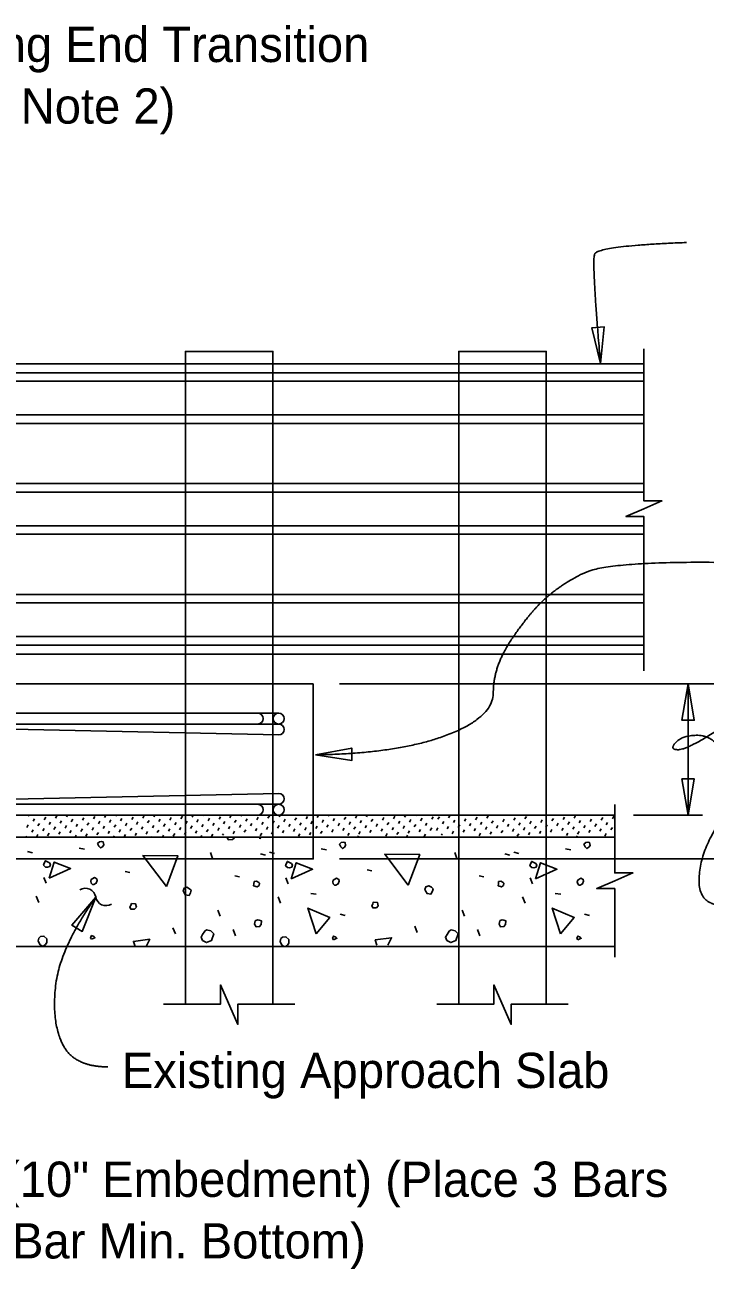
# Model space of a CAD drawing. Extents: x 1.5 to 68.7, y 0 to 31.
# Drawn here: x 32.97 to 36.86, y 9.34 to 16.45 of the extents above; entities that cross this region are included whole.
import ezdxf

# ---------------------------------------------------------------- set-up
doc = ezdxf.new("R2010")
doc.units = 0
for name, color, linetype in [('AdhocPoint_dp', 7, 'Continuous'), ('Border', 7, 'Continuous'), ('Patterning', 7, 'Continuous'), ('PlotBorder_dp', 7, 'Continuous'), ('TextMisc', 7, 'Continuous')]:
    doc.layers.add(name, color=color, linetype=linetype)

# ---------------------------------------------------------------- blocks, each defined once
blk = doc.blocks.new('Terminator-Arrow')
at = {"layer": 'AdhocPoint_dp'}
blk.add_lwpolyline([(0, 0), (-0.00041, 0.000069), (-0.00041, -0.000069)], close=True, dxfattribs=at)

msp = doc.modelspace()

# ---------------------------------------------------------------- linework, layer by layer
at = {"layer": 'AdhocPoint_dp'}
for p, q in [((34.7705, 12.682), (37.7448, 12.682)), ((36.763, 12.682), (36.763, 11.932)), ((36.4509, 11.932), (36.8456, 11.932)), ((34.7705, 11.682), (37.7448, 11.682))]:
    msp.add_line(p, q, dxfattribs=at)
for points in [[(36.2627, 14.5121), (36.2835, 14.7223), (36.2131, 14.7174)], [(34.6328, 12.277), (34.8416, 12.2452), (34.8404, 12.3157)], [(33.3771, 11.4646), (33.2393, 11.3045), (33.2997, 11.268)]]:
    msp.add_lwpolyline(points, close=True, dxfattribs=at)
for points in [[(36.5106, 12.7576), (36.5106, 13.6381), (36.4073, 13.6381), (36.5106, 13.6831), (36.6139, 13.7281), (36.5106, 13.7281), (36.5106, 14.5965)], [(36.3442, 11.1206), (36.3442, 11.5124), (36.2408, 11.5124), (36.3442, 11.5574), (36.4475, 11.6024), (36.3442, 11.6024), (36.3442, 11.9928)], [(34.5149, 10.8531), (34.1896, 10.8531), (34.1896, 10.7369), (34.0902, 10.9619), (34.0902, 10.8531), (33.7649, 10.8531)], [(36.0774, 10.8531), (35.7521, 10.8531), (35.7521, 10.7369), (35.6527, 10.9619), (35.6527, 10.8531), (35.3274, 10.8531)]]:
    msp.add_lwpolyline(points, dxfattribs=at)
for centre, start, end in [((33.3177, 11.455), 9.45289, 121.18011), ((33.4353, 11.4746), 189.45289, 301.18011)]:
    msp.add_arc(centre, 0.0596, start, end, dxfattribs=at)
for points in [[(36.7547, 15.2044), (36.2452, 15.1849), (36.212, 15.0904), (36.2626, 14.512)], [(36.9638, 13.3766), (36.3023, 13.3835), (36.0282, 13.2463), (35.8452, 13.0751), (35.6496, 12.7777), (35.6496, 12.4881), (35.1021, 12.2847), (34.6328, 12.2768)], [(36.9767, 11.4144), (36.8259, 11.4144), (36.8259, 11.6957), (37.0041, 11.9975), (37.0041, 12.217), (36.9013, 12.3885), (36.7299, 12.3885), (36.6545, 12.3062), (36.7573, 12.3062), (36.9287, 12.416)], [(33.4454, 10.4942), (33.2528, 10.4942), (33.1238, 10.7493), (33.172, 11.1721), (33.3771, 11.4644)]]:
    msp.add_open_spline(points, degree=2, dxfattribs=at)
at = {"layer": 'Border'}
for p, q in [((30.7872, 12.5153), (34.4226, 12.5153)), ((30.7872, 12.4528), (34.4226, 12.4528)), ((34.4226, 12.3904), (31.6205, 12.4528)), ((34.4226, 12.0569), (31.6205, 11.9945)), ((30.7872, 11.9945), (34.4226, 11.9945)), ((30.7872, 11.932), (34.4226, 11.932))]:
    msp.add_line(p, q, dxfattribs=at)
for centre in [(34.4226, 12.484), (34.4226, 11.9632)]:
    msp.add_circle(centre, 0.0312, dxfattribs=at)
for centre in [(34.3024, 12.4841), (34.4226, 12.4216), (34.4226, 12.4216), (34.4226, 12.0257), (34.3024, 11.9633)]:
    msp.add_arc(centre, 0.0312, 270, 90, dxfattribs=at)
at = {"layer": 'Patterning'}
for p, q in [((29.5056, 14.512), (36.5106, 14.512)), ((30.1632, 14.4598), (36.5106, 14.4598)), ((30.1645, 14.4116), (36.5106, 14.4116)), ((30.1692, 14.2188), (36.5106, 14.2188)), ((30.1703, 14.1705), (36.5106, 14.1705)), ((30.1669, 13.8266), (36.5106, 13.8266)), ((30.1656, 13.7783), (36.5106, 13.7783)), ((30.1604, 13.5855), (36.5106, 13.5855)), ((30.1563, 13.5374), (36.5106, 13.5374)), ((30.1703, 13.1934), (36.5106, 13.1934)), ((30.1692, 13.1452), (36.5106, 13.1452)), ((30.1629, 12.9524), (36.5106, 12.9524)), ((30.164, 12.9042), (36.5106, 12.9042)), ((29.5056, 12.8519), (36.5106, 12.8519)), ((32.9832, 11.8622), (32.9913, 11.8762)), ((32.9913, 11.9257), (32.9949, 11.932)), ((33.019, 11.898), (33.0271, 11.912)), ((33.0467, 11.8703), (33.0548, 11.8843)), ((33.0825, 11.9061), (33.0906, 11.9201)), ((33.1101, 11.8784), (33.1182, 11.8924)), ((33.1459, 11.9142), (33.154, 11.9282)), ((33.1736, 11.8865), (33.1817, 11.9005)), ((33.2013, 11.8588), (33.2094, 11.8728)), ((33.2094, 11.9223), (33.215, 11.932)), ((33.2371, 11.8946), (33.2452, 11.9086)), ((33.2648, 11.8669), (33.2729, 11.8809)), ((33.2729, 11.9304), (33.2738, 11.932)), ((33.3006, 11.9027), (33.3087, 11.9167)), ((33.3283, 11.875), (33.3364, 11.889)), ((33.3641, 11.9108), (33.3722, 11.9248)), ((33.3918, 11.8831), (33.3999, 11.8971)), ((33.4276, 11.9189), (33.4352, 11.932)), ((33.4553, 11.8912), (33.4634, 11.9052)), ((33.483, 11.8635), (33.4911, 11.8775)), ((33.4911, 11.927), (33.494, 11.932)), ((33.5188, 11.8993), (33.5269, 11.9133)), ((33.5465, 11.8716), (33.5546, 11.8856)), ((33.5823, 11.9074), (33.5904, 11.9214)), ((33.61, 11.8797), (33.6181, 11.8937)), ((33.6458, 11.9155), (33.6539, 11.9295)), ((33.6735, 11.8878), (33.6816, 11.9018)), ((33.7012, 11.8601), (33.7093, 11.8741)), ((33.7093, 11.9236), (33.7141, 11.932)), ((33.737, 11.8959), (33.7451, 11.9099)), ((33.7647, 11.8682), (33.7728, 11.8822)), ((33.7728, 11.9317), (33.7729, 11.932)), ((33.8005, 11.904), (33.8086, 11.918)), ((33.8282, 11.8763), (33.8363, 11.8903)), ((33.864, 11.9121), (33.8721, 11.9261)), ((33.8916, 11.8844), (33.8997, 11.8984)), ((33.9274, 11.9202), (33.9342, 11.932)), ((33.9551, 11.8925), (33.9632, 11.9065)), ((33.9828, 11.8648), (33.9909, 11.8788)), ((33.9909, 11.9283), (33.993, 11.932)), ((34.0186, 11.9006), (34.0267, 11.9146)), ((34.0463, 11.873), (34.0544, 11.8869)), ((34.0821, 11.9087), (34.0902, 11.9227)), ((34.1072, 11.8818), (34.1153, 11.8958)), ((34.143, 11.9176), (34.1511, 11.9316)), ((34.1707, 11.8899), (34.1788, 11.9039)), ((34.1984, 11.8622), (34.2065, 11.8762)), ((34.2065, 11.9257), (34.2102, 11.932)), ((34.2342, 11.898), (34.2423, 11.912)), ((34.2619, 11.8703), (34.27, 11.8843)), ((34.2977, 11.9061), (34.3058, 11.9201)), ((34.3254, 11.8784), (34.3335, 11.8924)), ((34.3612, 11.9142), (34.3693, 11.9282)), ((34.3889, 11.8865), (34.397, 11.9005)), ((34.4166, 11.8588), (34.4247, 11.8728)), ((34.4247, 11.9223), (34.4303, 11.932)), ((34.4524, 11.8946), (34.4605, 11.9086)), ((34.4801, 11.8669), (34.4882, 11.8809)), ((34.4882, 11.9304), (34.4891, 11.932)), ((34.5159, 11.9027), (34.524, 11.9167)), ((34.5436, 11.875), (34.5517, 11.889)), ((34.5794, 11.9108), (34.5875, 11.9248)), ((34.6071, 11.8831), (34.6152, 11.8971)), ((34.6429, 11.9189), (34.6504, 11.932)), ((34.6706, 11.8912), (34.6787, 11.9052)), ((34.6983, 11.8635), (34.7064, 11.8775)), ((34.7064, 11.927), (34.7092, 11.932)), ((34.7341, 11.8993), (34.7422, 11.9133)), ((34.7618, 11.8716), (34.7699, 11.8856)), ((34.7975, 11.9074), (34.8057, 11.9214)), ((34.8252, 11.8797), (34.8333, 11.8937)), ((34.861, 11.9155), (34.8691, 11.9295)), ((34.8887, 11.8878), (34.8968, 11.9018)), ((34.9164, 11.8601), (34.9245, 11.8741)), ((34.9245, 11.9236), (34.9294, 11.932)), ((34.9522, 11.8959), (34.9603, 11.9099)), ((34.9799, 11.8682), (34.988, 11.8822)), ((34.988, 11.9317), (34.9882, 11.932)), ((35.0157, 11.904), (35.0238, 11.918)), ((35.0434, 11.8763), (35.0515, 11.8903)), ((35.0792, 11.9121), (35.0873, 11.9261)), ((35.1069, 11.8844), (35.115, 11.8984)), ((35.1427, 11.9202), (35.1495, 11.932)), ((35.1704, 11.8925), (35.1785, 11.9065)), ((35.1981, 11.8648), (35.2062, 11.8788)), ((35.2062, 11.9283), (35.2083, 11.932)), ((35.2339, 11.9006), (35.242, 11.9146)), ((35.2616, 11.873), (35.2697, 11.8869)), ((35.2974, 11.9087), (35.3055, 11.9227)), ((35.3331, 11.9087), (35.3412, 11.9227)), ((35.3583, 11.8818), (35.3664, 11.8958)), ((35.3941, 11.9176), (35.4022, 11.9316)), ((35.4217, 11.8899), (35.4298, 11.9039)), ((35.4494, 11.8622), (35.4575, 11.8762)), ((35.4852, 11.898), (35.4933, 11.912)), ((35.5129, 11.8703), (35.521, 11.8843)), ((35.5487, 11.9061), (35.5568, 11.9201)), ((35.5764, 11.8784), (35.5845, 11.8924)), ((35.6122, 11.9142), (35.6203, 11.9282)), ((35.6399, 11.8865), (35.648, 11.9005)), ((35.6676, 11.8588), (35.6757, 11.8728)), ((35.7034, 11.8946), (35.7115, 11.9086)), ((35.7311, 11.8669), (35.7392, 11.8809)), ((35.7669, 11.9027), (35.775, 11.9167)), ((35.7946, 11.875), (35.8027, 11.889)), ((35.8304, 11.9108), (35.8385, 11.9248)), ((35.8581, 11.8831), (35.8662, 11.8971)), ((35.9216, 11.8912), (35.9297, 11.9052)), ((35.9493, 11.8635), (35.9574, 11.8775)), ((35.9851, 11.8993), (35.9932, 11.9133)), ((36.0128, 11.8716), (36.0209, 11.8856)), ((36.0486, 11.9074), (36.0567, 11.9214)), ((36.0763, 11.8797), (36.0844, 11.8937)), ((36.1121, 11.9155), (36.1202, 11.9295)), ((36.1398, 11.8878), (36.1479, 11.9018)), ((36.1675, 11.8601), (36.1756, 11.8741)), ((36.2032, 11.8959), (36.2113, 11.9099)), ((36.2309, 11.8682), (36.239, 11.8822)), ((36.2667, 11.904), (36.2748, 11.918)), ((36.2944, 11.8763), (36.3025, 11.8903)), ((36.3302, 11.9121), (36.3383, 11.9261)), ((32.9798, 11.807), (32.9832, 11.8127)), ((33.0109, 11.8345), (33.019, 11.8485)), ((33.0386, 11.807), (33.0467, 11.8208)), ((33.0743, 11.8426), (33.0825, 11.8566)), ((33.102, 11.8149), (33.1101, 11.8289)), ((33.1378, 11.8507), (33.1459, 11.8647)), ((33.1655, 11.823), (33.1736, 11.837)), ((33.2, 11.807), (33.2013, 11.8093)), ((33.229, 11.8311), (33.2371, 11.8451)), ((33.2588, 11.807), (33.2648, 11.8174)), ((33.2925, 11.8392), (33.3006, 11.8532)), ((33.3202, 11.8115), (33.3283, 11.8255)), ((33.356, 11.8473), (33.3641, 11.8613)), ((33.3837, 11.8196), (33.3918, 11.8336)), ((33.4195, 11.8554), (33.4276, 11.8694)), ((33.4472, 11.8277), (33.4553, 11.8417)), ((33.4789, 11.807), (33.483, 11.814)), ((33.5107, 11.8358), (33.5188, 11.8498)), ((33.5384, 11.8081), (33.5465, 11.8221)), ((33.5742, 11.8439), (33.5823, 11.8579)), ((33.6019, 11.8162), (33.61, 11.8302)), ((33.6377, 11.852), (33.6458, 11.866)), ((33.6654, 11.8243), (33.6735, 11.8383)), ((33.6991, 11.807), (33.7012, 11.8106)), ((33.7289, 11.8324), (33.737, 11.8464)), ((33.7579, 11.807), (33.7647, 11.8187)), ((33.7924, 11.8405), (33.8005, 11.8545)), ((33.8201, 11.8128), (33.8282, 11.8268)), ((33.8558, 11.8486), (33.864, 11.8626)), ((33.8835, 11.8209), (33.8916, 11.8349)), ((33.9192, 11.807), (33.9193, 11.8072)), ((33.9193, 11.8567), (33.9274, 11.8707)), ((33.947, 11.8291), (33.9551, 11.843)), ((33.978, 11.807), (33.9828, 11.8154)), ((34.0105, 11.8372), (34.0186, 11.8511)), ((34.0382, 11.8095), (34.0463, 11.8235)), ((34.074, 11.8453), (34.0821, 11.8593)), ((34.1017, 11.8176), (34.1067, 11.8263)), ((34.1349, 11.8541), (34.143, 11.8681)), ((34.1626, 11.8264), (34.1707, 11.8404)), ((34.2261, 11.8345), (34.2342, 11.8485)), ((34.2896, 11.8426), (34.2977, 11.8566)), ((34.3173, 11.8149), (34.3254, 11.8289)), ((34.3531, 11.8507), (34.3612, 11.8647)), ((34.3808, 11.823), (34.3889, 11.837)), ((34.4443, 11.8311), (34.4524, 11.8451)), ((34.5078, 11.8392), (34.5159, 11.8532)), ((34.5355, 11.8115), (34.5436, 11.8255)), ((34.5713, 11.8473), (34.5794, 11.8613)), ((34.595, 11.807), (34.5964, 11.8093)), ((34.599, 11.8196), (34.6071, 11.8336)), ((34.6348, 11.8554), (34.6429, 11.8694)), ((34.6625, 11.8277), (34.6706, 11.8417)), ((34.726, 11.8358), (34.7341, 11.8498)), ((34.7894, 11.8439), (34.7975, 11.8579)), ((34.8171, 11.8162), (34.8252, 11.8302)), ((34.8529, 11.852), (34.861, 11.866)), ((34.874, 11.807), (34.8781, 11.814)), ((34.8806, 11.8243), (34.8887, 11.8383)), ((34.9441, 11.8324), (34.9522, 11.8464)), ((35.0076, 11.8405), (35.0157, 11.8545)), ((35.0353, 11.8128), (35.0434, 11.8268)), ((35.0711, 11.8486), (35.0792, 11.8626)), ((35.0941, 11.807), (35.0962, 11.8106)), ((35.0988, 11.8209), (35.1069, 11.8349)), ((35.1346, 11.8567), (35.1427, 11.8707)), ((35.1529, 11.807), (35.1597, 11.8187)), ((35.1623, 11.8291), (35.1704, 11.843)), ((35.2258, 11.8372), (35.2339, 11.8511)), ((35.2535, 11.8095), (35.2616, 11.8235)), ((35.2893, 11.8453), (35.2974, 11.8593)), ((35.325, 11.8453), (35.3331, 11.8593)), ((35.3527, 11.8176), (35.3578, 11.8263)), ((35.3859, 11.8541), (35.3941, 11.8681)), ((35.4136, 11.8264), (35.4217, 11.8404)), ((35.4771, 11.8345), (35.4852, 11.8485)), ((35.5406, 11.8426), (35.5487, 11.8566)), ((35.5683, 11.8149), (35.5764, 11.8289)), ((35.6041, 11.8507), (35.6122, 11.8647)), ((35.6318, 11.823), (35.6399, 11.837)), ((35.6953, 11.8311), (35.7034, 11.8451)), ((35.7588, 11.8392), (35.7669, 11.8532)), ((35.7865, 11.8115), (35.7946, 11.8255)), ((35.8223, 11.8473), (35.8304, 11.8613)), ((35.8461, 11.807), (35.8474, 11.8093)), ((35.85, 11.8196), (35.8581, 11.8336)), ((35.8858, 11.8554), (35.8939, 11.8694)), ((35.9135, 11.8277), (35.9216, 11.8417)), ((35.977, 11.8358), (35.9851, 11.8498)), ((36.0405, 11.8439), (36.0486, 11.8579)), ((36.0682, 11.8162), (36.0763, 11.8302)), ((36.104, 11.852), (36.1121, 11.866)), ((36.125, 11.807), (36.1291, 11.814)), ((36.1317, 11.8243), (36.1398, 11.8383)), ((36.1951, 11.8324), (36.2032, 11.8464)), ((36.2586, 11.8405), (36.2667, 11.8545)), ((36.2863, 11.8128), (36.2944, 11.8268)), ((36.3221, 11.8486), (36.3302, 11.8626)), ((33.2826, 11.7433), (33.3126, 11.738)), ((34.6659, 11.7398), (34.6959, 11.7345)), ((36.0629, 11.7398), (36.093, 11.7345)), ((32.9869, 11.7243), (33.0152, 11.7173)), ((34.0445, 11.685), (34.0321, 11.7186)), ((34.3185, 11.7115), (34.3468, 11.7045)), ((34.3702, 11.7208), (34.3985, 11.7137)), ((35.4416, 11.685), (35.4292, 11.7186)), ((35.7156, 11.7115), (35.7439, 11.7045)), ((35.7673, 11.7208), (35.7956, 11.7137)), ((33.546, 11.6108), (33.5725, 11.6055)), ((34.9283, 11.619), (34.9549, 11.6137)), ((33.093, 11.5431), (33.0806, 11.5767)), ((34.1718, 11.586), (34.1983, 11.5807)), ((34.4763, 11.5396), (34.4639, 11.5732)), ((35.5689, 11.586), (35.5954, 11.5807)), ((35.8734, 11.5396), (35.861, 11.5732)), ((33.0506, 11.4335), (33.0364, 11.4689)), ((34.4338, 11.43), (34.4197, 11.4654)), ((34.6058, 11.4852), (34.6376, 11.4817)), ((35.8309, 11.43), (35.8168, 11.4654)), ((36.0028, 11.4852), (36.0347, 11.4817)), ((34.0887, 11.3544), (34.0745, 11.3898)), ((35.4858, 11.3544), (35.4716, 11.3898)), ((34.7737, 11.3668), (34.802, 11.3597)), ((36.1708, 11.3668), (36.1991, 11.3597)), ((33.8324, 11.2537), (33.8182, 11.289)), ((34.1757, 11.2426), (34.1616, 11.278)), ((35.2147, 11.2619), (35.2006, 11.2972)), ((35.5728, 11.2426), (35.5587, 11.278))]:
    msp.add_line(p, q, dxfattribs=at)
for points in [[(34.3899, 10.853), (34.3899, 14.5819), (33.8899, 14.5819), (33.8899, 10.853)], [(35.9524, 10.853), (35.9524, 14.5819), (35.4524, 14.5819), (35.4524, 10.853)], [(34.1266, 11.8069), (34.1364, 11.7911), (34.1594, 11.7928), (34.1682, 11.8017), (34.1735, 11.8069)], [(34.3154, 11.7968), (34.3121, 11.8069)], [(34.3206, 11.8069), (34.3154, 11.7968)], [(33.3939, 11.7557), (33.4046, 11.7451), (33.4152, 11.7522), (33.4222, 11.7628), (33.4187, 11.7805), (33.4099, 11.7822), (33.3975, 11.7805), (33.3869, 11.7699), (33.3939, 11.7557)], [(34.7772, 11.7522), (34.7878, 11.7416), (34.7984, 11.7486), (34.8055, 11.7593), (34.802, 11.7769), (34.7931, 11.7787), (34.7808, 11.7769), (34.7702, 11.7663), (34.7772, 11.7522)], [(36.1743, 11.7522), (36.1849, 11.7416), (36.1955, 11.7486), (36.2026, 11.7593), (36.1991, 11.7769), (36.1902, 11.7787), (36.1778, 11.7769), (36.1672, 11.7663), (36.1743, 11.7522)], [(33.0895, 11.636), (33.1018, 11.6342), (33.1142, 11.6395), (33.1177, 11.6501), (33.1124, 11.6589), (33.1018, 11.666), (33.0895, 11.6713), (33.0824, 11.6572), (33.0788, 11.6466), (33.0895, 11.636)], [(33.1111, 11.5719), (33.1394, 11.6638), (33.2331, 11.6267), (33.1111, 11.5719)], [(33.7811, 11.5241), (33.6467, 11.7009), (33.8465, 11.6991), (33.7811, 11.5241)], [(34.4727, 11.6324), (34.4851, 11.6306), (34.4975, 11.636), (34.501, 11.6466), (34.4957, 11.6554), (34.4851, 11.6625), (34.4727, 11.6678), (34.4657, 11.6536), (34.4621, 11.643), (34.4727, 11.6324)], [(34.4944, 11.5683), (34.5227, 11.6603), (34.6164, 11.6231), (34.4944, 11.5683)], [(35.1634, 11.5323), (35.0291, 11.7091), (35.2289, 11.7074), (35.1634, 11.5323)], [(35.8698, 11.6324), (35.8822, 11.6306), (35.8946, 11.636), (35.8981, 11.6466), (35.8928, 11.6554), (35.8822, 11.6625), (35.8698, 11.6678), (35.8627, 11.6536), (35.8592, 11.643), (35.8698, 11.6324)], [(35.8915, 11.5683), (35.9198, 11.6603), (36.0134, 11.6231), (35.8915, 11.5683)], [(33.3586, 11.5365), (33.3657, 11.5365), (33.3798, 11.5436), (33.3851, 11.5595), (33.3833, 11.5683), (33.3692, 11.5754), (33.3515, 11.5648), (33.348, 11.5542), (33.3515, 11.5436), (33.3586, 11.5365)], [(33.8801, 11.4923), (33.8889, 11.4764), (33.9101, 11.4729), (33.919, 11.4888), (33.9225, 11.5029), (33.9137, 11.5118), (33.8978, 11.5206), (33.8819, 11.5153), (33.8765, 11.4994), (33.8801, 11.4923)], [(34.2796, 11.5277), (34.299, 11.5224), (34.3114, 11.5312), (34.3132, 11.5436), (34.3097, 11.5471), (34.2955, 11.5542), (34.2831, 11.5524), (34.2814, 11.54), (34.2796, 11.5277)], [(34.7419, 11.533), (34.7489, 11.533), (34.7631, 11.54), (34.7684, 11.556), (34.7666, 11.5648), (34.7525, 11.5719), (34.7348, 11.5613), (34.7313, 11.5507), (34.7348, 11.54), (34.7419, 11.533)], [(35.2624, 11.5005), (35.2713, 11.4846), (35.2925, 11.4811), (35.3013, 11.497), (35.3049, 11.5111), (35.296, 11.52), (35.2801, 11.5288), (35.2642, 11.5235), (35.2589, 11.5076), (35.2624, 11.5005)], [(35.6767, 11.5277), (35.6961, 11.5224), (35.7085, 11.5312), (35.7103, 11.5436), (35.7067, 11.5471), (35.6926, 11.5542), (35.6802, 11.5524), (35.6785, 11.54), (35.6767, 11.5277)], [(36.139, 11.533), (36.146, 11.533), (36.1602, 11.54), (36.1655, 11.556), (36.1637, 11.5648), (36.1496, 11.5719), (36.1319, 11.5613), (36.1284, 11.5507), (36.1319, 11.54), (36.139, 11.533)], [(33.5778, 11.3951), (33.599, 11.3951), (33.6096, 11.4057), (33.6043, 11.4251), (33.5813, 11.4269), (33.5778, 11.4163), (33.5725, 11.4075), (33.5778, 11.3951), (33.5743, 11.3986)], [(34.6371, 11.255), (34.5894, 11.4017), (34.7149, 11.3469), (34.6371, 11.255)], [(34.9602, 11.4033), (34.9814, 11.4033), (34.992, 11.4139), (34.9867, 11.4334), (34.9637, 11.4351), (34.9602, 11.4245), (34.9549, 11.4157), (34.9602, 11.4033), (34.9566, 11.4068)], [(36.0342, 11.255), (35.9865, 11.4017), (36.112, 11.3469), (36.0342, 11.255)], [(34.2853, 11.3098), (34.2942, 11.2939), (34.3136, 11.2957), (34.3225, 11.308), (34.3242, 11.3275), (34.3119, 11.3328), (34.303, 11.3345), (34.2924, 11.331), (34.2889, 11.3275), (34.2853, 11.3098)], [(35.6824, 11.3098), (35.6913, 11.2939), (35.7107, 11.2957), (35.7196, 11.308), (35.7213, 11.3275), (35.7089, 11.3328), (35.7001, 11.3345), (35.6895, 11.331), (35.686, 11.3275), (35.6824, 11.3098)], [(33.047, 11.2143), (33.0576, 11.1931), (33.0753, 11.1825), (33.0895, 11.1931), (33.0965, 11.2037), (33.0965, 11.2249), (33.0806, 11.2409), (33.0612, 11.2391), (33.0523, 11.2302), (33.047, 11.2143)], [(33.3528, 11.2232), (33.3723, 11.232), (33.3652, 11.2391), (33.3528, 11.2444), (33.3475, 11.232), (33.3528, 11.2232)], [(33.9862, 11.2165), (34.0091, 11.2042), (34.0392, 11.2165), (34.0516, 11.2537), (34.0339, 11.2713), (34.0109, 11.2767), (34.0003, 11.2696), (33.9879, 11.2501), (33.9791, 11.2342), (33.9862, 11.2165)], [(34.4625, 11.1819), (34.4727, 11.1896), (34.4798, 11.2002), (34.4798, 11.2214), (34.4639, 11.2373), (34.4444, 11.2356), (34.4356, 11.2267), (34.4303, 11.2108)], [(34.7361, 11.2196), (34.7556, 11.2285), (34.7485, 11.2356), (34.7361, 11.2409), (34.7308, 11.2285), (34.7361, 11.2196)], [(35.3832, 11.2165), (35.4062, 11.2042), (35.4363, 11.2165), (35.4486, 11.2537), (35.431, 11.2713), (35.408, 11.2767), (35.3974, 11.2696), (35.385, 11.2501), (35.3762, 11.2342), (35.3832, 11.2165)], [(36.1332, 11.2196), (36.1527, 11.2285), (36.1456, 11.2356), (36.1332, 11.2409), (36.1279, 11.2285), (36.1332, 11.2196)], [(33.6014, 11.1819), (33.5919, 11.2112), (33.6856, 11.2236), (33.6642, 11.1819)], [(34.4303, 11.2108), (34.4409, 11.1896), (34.4537, 11.1819)], [(34.9837, 11.1901), (34.9743, 11.2195), (35.068, 11.2318), (35.0465, 11.1901)]]:
    msp.add_lwpolyline(points, dxfattribs=at)
at = {"layer": 'PlotBorder_dp'}
for p, q in [((25.4726, 12.682), (34.6205, 12.682)), ((31.6205, 12.682), (34.6205, 12.682)), ((34.6205, 12.682), (34.6205, 11.932)), ((34.6205, 12.682), (34.6205, 11.932)), ((31.3067, 11.932), (36.344, 11.932)), ((31.2771, 11.807), (36.344, 11.807)), ((30.6926, 11.182), (36.344, 11.182))]:
    msp.add_line(p, q, dxfattribs=at)
msp.add_lwpolyline([(34.6205, 11.932), (34.6205, 11.682), (31.6205, 11.682), (31.6205, 11.932)], dxfattribs=at)

# ---------------------------------------------------------------- block references
at = {"layer": 'AdhocPoint_dp', "xscale": 506.349, "yscale": -512.1577380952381}
for p, rotation in [((36.7628, 12.6817), 90), ((36.7628, 11.9318), -90)]:
    msp.add_blockref('Terminator-Arrow', p, dxfattribs=dict(at, rotation=rotation))

# ---------------------------------------------------------------- texts
at = {"layer": 'AdhocPoint_dp'}
for s, p in [('Railing End Transition ', (32.3035, 16.2355)), ('(See Note 2)', (32.3035, 15.8835)), ('Dowel Bars 4L (10" Embedment) (Place 3 Bars ', (31.0251, 9.7512)), ('Min. Top and 1 Bar Min. Bottom)', (31.0251, 9.3992))]:
    msp.add_text(s, height=0.2016, dxfattribs=at).set_placement(p)
at = {"layer": 'TextMisc'}
msp.add_text('Existing Approach Slab', height=0.2016, dxfattribs=at).set_placement((33.526, 10.3731))

doc.saveas('drawing.dxf')
